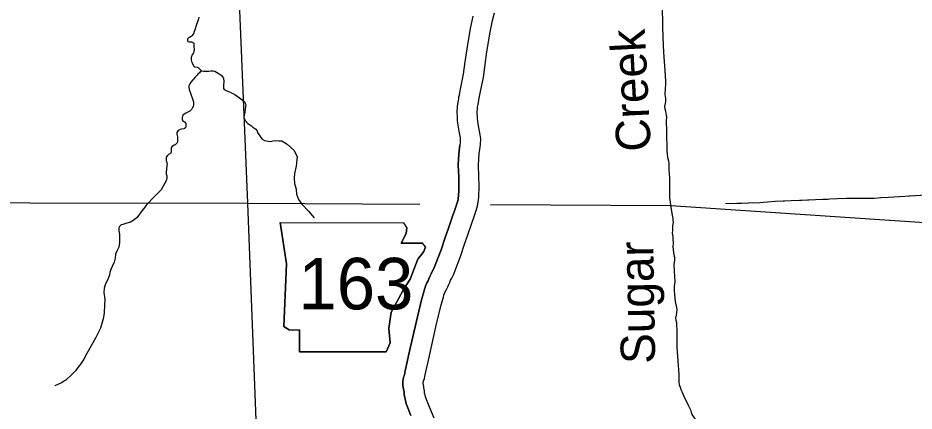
# Model space of a CAD drawing. Extents: x 1720274 to 1751788, y 372074 to 391887.
# Drawn here: x 1732023 to 1733764, y 380014 to 380778 of the extents above; entities that cross this region are included whole.
import ezdxf

# ---------------------------------------------------------------- set-up
doc = ezdxf.new("R2010")
doc.units = 0
for name, color, linetype in [('Level 10', 7, 'Continuous'), ('Level 21', 7, 'Continuous'), ('Level 35', 7, 'Continuous'), ('Level 43', 7, 'Continuous'), ('Level 49', 7, 'Continuous'), ('Level 5', 7, 'Continuous')]:
    doc.layers.add(name, color=color, linetype=linetype)

msp = doc.modelspace()

# ---------------------------------------------------------------- linework, layer by layer
at = {"layer": 'Level 10'}
for points in [[(1732921, 380526.3), (1732921.8, 380533.1), (1732922.3, 380543.1), (1732921.2, 380551.1), (1732918.9, 380565.1), (1732917, 380576.1), (1732916.5, 380578.8), (1732916.2, 380581.7), (1732916.1, 380584.1), (1732916.1, 380587.4), (1732915.8, 380590.9), (1732915.7, 380593.2), (1732915.7, 380595.9), (1732915.7, 380597.6), (1732915.9, 380599.9), (1732916.1, 380602.8), (1732916.4, 380604.9), (1732916.7, 380607.3), (1732917.3, 380610), (1732918.1, 380614.3), (1732918.5, 380617.6), (1732919, 380620), (1732919.4, 380622.3), (1732922.7, 380638.6), (1732927.5, 380662.3), (1732931, 380687.6), (1732934.2, 380712.2), (1732940.9, 380750.3), (1732945.4, 380773.2), (1732949.2, 380788.3)], [(1732906.9, 380781.8), (1732902.1, 380757.5), (1732895.1, 380718.2), (1732891.8, 380692.8), (1732888.5, 380668.9), (1732884, 380646.5), (1732880.6, 380629.5), (1732880.3, 380627.7), (1732879.5, 380624.3), (1732879, 380620.3), (1732878.6, 380617.7), (1732877.8, 380614.3), (1732877.2, 380609.9), (1732876.8, 380606.7), (1732876.5, 380603), (1732876.2, 380599), (1732876.2, 380595.9), (1732876.2, 380592.2), (1732876.4, 380588.5), (1732876.6, 380586), (1732876.6, 380582.8), (1732876.9, 380578.6), (1732877.3, 380573.7), (1732878, 380569.5), (1732879.9, 380558.4), (1732882.2, 380545.2), (1732882.6, 380541.5), (1732882.4, 380536.2), (1732881.8, 380530.6)], [(1732797, 380186.6), (1732807.6, 380230.6), (1732811.8, 380245.7), (1732813.2, 380251.1), (1732815.3, 380257), (1732817.9, 380263.1), (1732820.2, 380267.3), (1732821.8, 380271.1), (1732823.6, 380275.6), (1732826.3, 380280.7), (1732828.2, 380285.4), (1732830.8, 380290.1), (1732832.8, 380294.3), (1732845.6, 380327.6), (1732852.8, 380349.6), (1732860.1, 380369.6), (1732867.1, 380390.7), (1732871.7, 380403.1), (1732875.6, 380415.2), (1732877.8, 380423), (1732878.7, 380426.8), (1732878.9, 380428.3), (1732879, 380431.7), (1732879.2, 380435.4), (1732879.6, 380440.3), (1732879.6, 380443.7), (1732879.6, 380448), (1732879.8, 380452.6), (1732879.6, 380468.6), (1732878.9, 380492.1), (1732879, 380505.1), (1732880.4, 380519.7), (1732881.8, 380530.6)], [(1732881.8, 380530.6), (1732880.4, 380519.7), (1732879, 380505.1), (1732878.9, 380492.1), (1732879.6, 380468.6), (1732879.8, 380452.6), (1732879.6, 380448), (1732879.6, 380443.7), (1732879.6, 380440.3), (1732879.2, 380435.4), (1732879, 380431.7), (1732878.9, 380428.3), (1732878.7, 380426.8), (1732877.8, 380423), (1732875.6, 380415.2), (1732871.7, 380403.1), (1732867.1, 380390.7), (1732860.1, 380369.6), (1732852.8, 380349.6), (1732845.6, 380327.6), (1732832.8, 380294.3), (1732830.8, 380290.1), (1732828.2, 380285.4), (1732826.3, 380280.7), (1732823.6, 380275.6), (1732821.8, 380271.1), (1732820.2, 380267.3), (1732817.9, 380263.1), (1732815.3, 380257), (1732813.2, 380251.1), (1732811.8, 380245.7), (1732807.6, 380230.6), (1732797, 380186.6)], [(1732835.5, 380177.6), (1732845.8, 380220.7), (1732849.9, 380235.3), (1732850.9, 380239.2), (1732852.1, 380242.5), (1732853.6, 380246), (1732855.9, 380250.3), (1732858.2, 380255.8), (1732859.5, 380258.8), (1732862.2, 380264.1), (1732864, 380268.4), (1732866.1, 380272.4), (1732869.2, 380278.9), (1732882.8, 380314.3), (1732890.2, 380336.7), (1732897.4, 380356.6), (1732904.4, 380377.5), (1732909.1, 380390.2), (1732913.5, 380403.9), (1732916.1, 380413.2), (1732917.6, 380420), (1732918.2, 380424.8), (1732918.5, 380429.8), (1732918.6, 380433.1), (1732919, 380438.4), (1732919.1, 380443.2), (1732919.1, 380447.2), (1732919.3, 380452.2), (1732919, 380469.5), (1732918.4, 380492.6), (1732918.5, 380503), (1732919.7, 380515.4), (1732921, 380526.3)], [(1732786.8, 380005.8), (1732778.3, 380027.1), (1732777.2, 380031.3), (1732776.3, 380034.7), (1732775.4, 380038.1), (1732774.9, 380039.8), (1732774.3, 380042.9), (1732773.9, 380046.2), (1732773.7, 380048.7), (1732773.4, 380050.8), (1732773, 380053.9), (1732772.7, 380055.8), (1732772.3, 380057.9), (1732772, 380059.7), (1732771.4, 380063.2), (1732771.2, 380067.3), (1732771.3, 380071.4), (1732771.6, 380075.7), (1732772.6, 380080), (1732773.4, 380082.9), (1732774.2, 380085.5), (1732774.7, 380087.3), (1732775.2, 380089.5), (1732775.7, 380092.2), (1732784.2, 380130.3), (1732797, 380186.6)], [(1732797, 380186.6), (1732784.2, 380130.3), (1732775.7, 380092.2), (1732775.2, 380089.5), (1732774.7, 380087.3), (1732774.2, 380085.5), (1732773.4, 380082.9), (1732772.6, 380080), (1732771.6, 380075.7), (1732771.3, 380071.4), (1732771.2, 380067.3), (1732771.4, 380063.2), (1732772, 380059.7), (1732772.3, 380057.9), (1732772.7, 380055.8), (1732773, 380053.9), (1732773.4, 380050.8), (1732773.7, 380048.7), (1732773.9, 380046.2), (1732774.3, 380042.9), (1732774.9, 380039.8), (1732775.4, 380038.1), (1732776.3, 380034.7), (1732777.2, 380031.3), (1732778.3, 380027.1), (1732786.8, 380005.8)], [(1732831.8, 380000.2), (1732823.4, 380020.6), (1732815.9, 380039.7), (1732815.3, 380041.7), (1732814.4, 380044.9), (1732813.6, 380048.2), (1732813.5, 380048.5), (1732813.4, 380049), (1732813.2, 380050.1), (1732813, 380053.5), (1732812.4, 380056.8), (1732812.1, 380059.2), (1732811.7, 380062.2), (1732811.1, 380065.3), (1732810.9, 380066.7), (1732810.8, 380067.3), (1732810.7, 380067.8), (1732810.8, 380069.6), (1732810.8, 380069.6), (1732810.9, 380070.2), (1732811.4, 380072), (1732812.1, 380074.5), (1732813, 380077.4), (1732813.9, 380081.4), (1732814.4, 380084.3), (1732822.7, 380121.6), (1732835.5, 380177.6)]]:
    msp.add_lwpolyline(points, dxfattribs=at)
at = {"layer": 'Level 21'}
for p, q in [((1732532.9, 380380.4), (1732544.9, 380300.2)), ((1732778.8, 380371), (1732773.3, 380380.2)), ((1732777.5, 380359), (1732778.8, 380371)), ((1732768.1, 380340.3), (1732777.5, 380359)), ((1732809.5, 380340.3), (1732768.1, 380340.3)), ((1732814.9, 380333.6), (1732809.5, 380340.3)), ((1732800.2, 380309.5), (1732812.2, 380324.2)), ((1732812.2, 380324.2), (1732814.9, 380333.6)), ((1732544.9, 380300.2), (1732539.6, 380178.6)), ((1732793.5, 380292.2), (1732800.2, 380309.5)), ((1732785.5, 380270.8), (1732793.5, 380292.2)), ((1732772.1, 380250.7), (1732785.5, 380270.8)), ((1732762.8, 380232), (1732772.1, 380250.7)), ((1732748.1, 380206.6), (1732762.8, 380232)), ((1732744, 380174.5), (1732748.1, 380206.6)), ((1732539.6, 380178.6), (1732550.3, 380171.9)), ((1732550.3, 380171.9), (1732570.3, 380171.9)), ((1732570.3, 380171.9), (1732570.3, 380129.1)), ((1732746.7, 380146.5), (1732744, 380174.5)), ((1732738.7, 380129.1), (1732746.7, 380146.5)), ((1732570.3, 380129.1), (1732738.7, 380129.1))]:
    msp.add_line(p, q, dxfattribs=at)
msp.add_lwpolyline([(1732532.9, 380380.4), (1732773.3, 380380.2)], dxfattribs=at)
at = {"layer": 'Level 35'}
for points in [[(1733275.1, 380802), (1733275.4, 380762.3), (1733276, 380740.9), (1733277.8, 380710.9), (1733280.2, 380675.9), (1733281.5, 380654.9), (1733281.3, 380649), (1733280.6, 380640.9), (1733280.2, 380629.1), (1733281.3, 380621.6), (1733281.1, 380616.8), (1733280.7, 380611.7), (1733279.5, 380606), (1733280, 380601.4), (1733281.5, 380596.7), (1733282.8, 380589.3), (1733283.5, 380586.2), (1733282.8, 380577.6), (1733283.5, 380557.9), (1733284, 380518.9), (1733285.5, 380507.4), (1733287.1, 380500.4), (1733287.9, 380495.3), (1733287.9, 380491.3), (1733287.7, 380482.7), (1733289, 380467.5), (1733289, 380428.1), (1733290.2, 380421), (1733291.3, 380414), (1733293.5, 380397.9), (1733295.4, 380388.6), (1733295.9, 380384.4), (1733296.1, 380380.5), (1733295.9, 380377.6), (1733295.2, 380374), (1733295, 380370.3), (1733294.8, 380365), (1733294.6, 380359.9), (1733295.7, 380352.9), (1733295.7, 380348), (1733296.3, 380341.4), (1733295.6, 380333.2), (1733296.1, 380328.8), (1733297.2, 380321.8), (1733298.8, 380311.7), (1733298.8, 380307.3), (1733297.7, 380299.3), (1733298.1, 380286.1), (1733299, 380275.9), (1733299.6, 380265.4), (1733298.5, 380256.1), (1733298.5, 380249), (1733298.8, 380240), (1733299.2, 380234.2), (1733300.3, 380227), (1733302.5, 380215.3), (1733303.2, 380211.1), (1733302.7, 380205.6), (1733302.1, 380200.8), (1733300.9, 380194.8), (1733301.6, 380191.1), (1733303, 380186.6), (1733303.6, 380166.6), (1733303.2, 380137.7), (1733307.3, 380085.4), (1733307, 380070.7)], [(1732374.8, 380779.3), (1732373.9, 380775.5), (1732371.8, 380768.9), (1732370.5, 380765.5), (1732366.9, 380754.7), (1732365.5, 380751.8), (1732365.1, 380749.5), (1732364.8, 380747.8), (1732364, 380746.3), (1732361.4, 380743.3), (1732360.1, 380742), (1732356.4, 380740.1), (1732354.2, 380738.5), (1732352.9, 380737.5), (1732352.6, 380736.7), (1732352.6, 380735.6), (1732352.6, 380734.6), (1732352.6, 380733.7), (1732353, 380733.3), (1732353.6, 380732.5), (1732355.4, 380732), (1732357.8, 380732), (1732360.4, 380731.7), (1732362.3, 380731.2), (1732363.3, 380730.7), (1732364.8, 380729.4), (1732365.2, 380727.6), (1732365.2, 380725.3), (1732365.3, 380721.7), (1732365.9, 380717), (1732365.9, 380715.2), (1732365.3, 380713.3), (1732365.1, 380711.4), (1732363.6, 380708.8), (1732361.4, 380705.7), (1732360.4, 380703.3), (1732359.7, 380701.5), (1732359.7, 380699.7), (1732359.7, 380697.6), (1732360.4, 380693.6), (1732361.6, 380691.1), (1732364.3, 380684.9), (1732366.6, 380683.1), (1732367.8, 380683), (1732371.7, 380682.7), (1732373.4, 380681.8), (1732376.3, 380679.2), (1732377.8, 380677.1), (1732379.8, 380675.3), (1732383.6, 380674.6), (1732385.9, 380674.6), (1732388.8, 380674.4), (1732394.4, 380674.9), (1732398.3, 380675.6), (1732402.5, 380675.3), (1732405.9, 380674.4), (1732409.3, 380673), (1732412.4, 380670.8), (1732418.3, 380666.9)], [(1732379.5, 380675.7), (1732376, 380671.6), (1732372.6, 380668.6), (1732371.4, 380667.2), (1732369.1, 380664.5), (1732367.7, 380662.9), (1732364.2, 380658.9), (1732363.2, 380658.1), (1732359, 380653.2), (1732357.5, 380650.3), (1732355.5, 380646.1), (1732355.1, 380643.4), (1732355.9, 380639.2), (1732359.5, 380629.7), (1732362.4, 380621.2), (1732364.2, 380614.8), (1732364.2, 380610.5), (1732364.2, 380607.1), (1732362.1, 380602.8), (1732360.6, 380600.4), (1732357.2, 380597.1), (1732353.4, 380595.1), (1732348, 380592.5), (1732343.9, 380589.2), (1732343.4, 380588.1), (1732342.4, 380585), (1732342.4, 380583), (1732342.4, 380580.7), (1732342.9, 380578.9), (1732347, 380576.1), (1732349.3, 380572.7), (1732349.5, 380570.4), (1732349.5, 380567.6), (1732348.8, 380564.5), (1732347, 380563), (1732345.4, 380562.5), (1732341.1, 380561.7), (1732338.5, 380561.4), (1732334.9, 380559.1), (1732332.1, 380555.3), (1732331.9, 380552.2), (1732333.6, 380547.3), (1732333.6, 380542.4), (1732333.1, 380538.3), (1732332.4, 380535.5), (1732330.6, 380533.2), (1732328.5, 380531.4), (1732327, 380530.6), (1732322.4, 380527.8), (1732321.3, 380525.8), (1732321.3, 380522.9), (1732321.3, 380521.1), (1732321.3, 380518.3), (1732320.1, 380515.5), (1732316, 380512.7), (1732313.6, 380510.6), (1732311.3, 380507.8), (1732311.1, 380506), (1732311.1, 380503.2), (1732311.6, 380500.9), (1732313.1, 380494.7), (1732312.9, 380490.8), (1732311.1, 380478.3), (1732311.6, 380474.9), (1732312.4, 380471.3), (1732312.4, 380467.2), (1732311.3, 380461.6), (1732309, 380457.2), (1732301.3, 380444.4), (1732294.2, 380436.7), (1732287.2, 380429.8), (1732273.9, 380415.6), (1732260.6, 380398.7), (1732255.2, 380390.2), (1732247.2, 380384.3), (1732241.8, 380381), (1732234.9, 380379.5), (1732227.2, 380376.9), (1732223.9, 380375.9), (1732220.6, 380372.8), (1732219.3, 380370), (1732219.5, 380364.3), (1732220.6, 380358.2), (1732220.8, 380349.4), (1732220.6, 380342), (1732219.3, 380333), (1732215.2, 380324.8), (1732213.1, 380318.9), (1732212.1, 380311.4), (1732210.3, 380303.7), (1732206.2, 380295.3), (1732203.9, 380289.4), (1732201.8, 380283.5), (1732201.3, 380278.1), (1732199.5, 380273.7), (1732197.2, 380268.3), (1732193.6, 380261.6), (1732191.1, 380253.2), (1732190.3, 380244.2), (1732191.3, 380237), (1732192.3, 380229.8)], [(1732418.3, 380666.9), (1732420.5, 380663.9), (1732422.4, 380661), (1732422.7, 380659.4), (1732423.4, 380655.8), (1732423.4, 380653), (1732422.9, 380648.8), (1732422.8, 380645.9), (1732422.7, 380643.6), (1732422.7, 380642), (1732422.9, 380641.1), (1732424.1, 380639.2), (1732425.3, 380638.1), (1732428.9, 380636.3), (1732434.4, 380634.3), (1732444.8, 380629.1), (1732451.2, 380624.9), (1732453.6, 380622.6), (1732459.1, 380618.8), (1732462.2, 380616.5), (1732463.9, 380614.2), (1732464.9, 380611.9), (1732465.8, 380609), (1732465.6, 380605.3), (1732464.9, 380600.9), (1732464.3, 380595.3), (1732463, 380588.3), (1732462.3, 380584.9), (1732462.5, 380582.5), (1732464.6, 380578.8), (1732470.1, 380573), (1732477.2, 380568.4), (1732480, 380565.8), (1732485.5, 380561.7), (1732487.9, 380558.4), (1732489, 380555.2), (1732491.3, 380551.9), (1732493, 380548.7), (1732495, 380545.7), (1732498.1, 380542.6), (1732502.4, 380539.7), (1732509.9, 380538.4), (1732513.8, 380538.3), (1732518.9, 380539.4), (1732523.5, 380540), (1732529.9, 380539.4), (1732535.7, 380539.4), (1732546.1, 380532.8), (1732559.6, 380521.4), (1732565.8, 380509), (1732565.3, 380503.3), (1732563.8, 380489.8), (1732560.6, 380475.8), (1732560.1, 380467), (1732560.6, 380456.1), (1732563.8, 380445.2), (1732564.8, 380435.9), (1732568.4, 380425.5), (1732574.6, 380416.2), (1732588.1, 380402.7), (1732598.6, 380389.8)], [(1732192.3, 380229.8), (1732191.6, 380221.3), (1732190.8, 380204.4), (1732188.8, 380193.1), (1732183.9, 380175.4), (1732174.9, 380157.4), (1732157.2, 380125.9), (1732151.1, 380115.1), (1732144.9, 380105.1), (1732139.8, 380098.9), (1732135.2, 380092.5), (1732127.2, 380084.8), (1732116.4, 380074.3), (1732108.2, 380068.9), (1732094.9, 380063.5)], [(1733307, 380070.7), (1733307.8, 380065.6), (1733310.6, 380058.5), (1733311.5, 380055), (1733312.8, 380052.2), (1733316.9, 380043.4), (1733326.3, 380024.6), (1733329.9, 380016.8), (1733331.2, 380011.4), (1733332.8, 380007.5), (1733337, 380001.3), (1733343.4, 379994), (1733356.4, 379982.6), (1733372.9, 379965.2)]]:
    msp.add_lwpolyline(points, dxfattribs=at)
at = {"layer": 'Level 43'}
for points in [[(1733397.9, 380417.4), (1733464.5, 380419.5), (1733494.6, 380421.9), (1733572.8, 380425.2), (1733614.9, 380427), (1733632.8, 380427.7), (1733654.6, 380428.1), (1733686.8, 380428.1), (1733700.4, 380428.9), (1733714.4, 380429.7), (1733746.3, 380432), (1733837.2, 380437.5), (1733888.1, 380440.2), (1733929.7, 380442.9), (1733949.1, 380443.7), (1733957.6, 380444.9), (1733969.7, 380447.2), (1733989.2, 380452)], [(1733450, 380419.1), (1733464.5, 380419.5), (1733494.6, 380421.9), (1733512.4, 380422.7)], [(1733533.3, 380423.5), (1733572.8, 380425.2), (1733595.8, 380426.2)], [(1733616.6, 380427), (1733632.8, 380427.7), (1733654.6, 380428.1), (1733679.2, 380428.1)], [(1733700, 380428.9), (1733700.4, 380428.9), (1733714.4, 380429.7), (1733746.3, 380432), (1733762.4, 380433)], [(1733397.9, 380417.4), (1733429.1, 380418.4)]]:
    msp.add_lwpolyline(points, dxfattribs=at)
at = {"layer": 'Level 49'}
for p, q in [((1732544.9, 380300.2), (1732532.9, 380380.4)), ((1732778.8, 380371), (1732777.5, 380359)), ((1732777.5, 380359), (1732768.1, 380340.3)), ((1732768.1, 380340.3), (1732809.5, 380340.3)), ((1732812.2, 380324.2), (1732800.2, 380309.5)), ((1732814.9, 380333.6), (1732812.2, 380324.2)), ((1732539.6, 380178.6), (1732544.9, 380300.2)), ((1732800.2, 380309.5), (1732793.5, 380292.2)), ((1732793.5, 380292.2), (1732785.5, 380270.8)), ((1732785.5, 380270.8), (1732772.1, 380250.7)), ((1732772.1, 380250.7), (1732762.8, 380232)), ((1732762.8, 380232), (1732748.1, 380206.6)), ((1732748.1, 380206.6), (1732744, 380174.5)), ((1732550.3, 380171.9), (1732539.6, 380178.6)), ((1732570.3, 380129.1), (1732570.3, 380171.9)), ((1732744, 380174.5), (1732746.7, 380146.5)), ((1732746.7, 380146.5), (1732738.7, 380129.1)), ((1732738.7, 380129.1), (1732570.3, 380129.1))]:
    msp.add_line(p, q, dxfattribs=at)
msp.add_lwpolyline([(1732532.9, 380380.4), (1732773.3, 380380.2)], dxfattribs=at)
at = {"layer": 'Level 5'}
for points in [[(1732434.1, 381262.1), (1732469.3, 380417.9)], [(1731623, 380419.3), (1732469.3, 380417.9)], [(1732469.3, 380417.9), (1732501.6, 379574.7)], [(1732469.3, 380417.9), (1732803.8, 380416.1)], [(1732941.4, 380415.4), (1733291.7, 380413.5)], [(1733291.7, 380413.5), (1734056.1, 380362.4)]]:
    msp.add_lwpolyline(points, dxfattribs=at)

# ---------------------------------------------------------------- texts
at = {"layer": 'Level 21'}
msp.add_text('163', height=100.11, dxfattribs=at).set_placement((1732568.2, 380211.8))
at = {"layer": 'Level 35'}
for s, rotation, p in [('Creek', 92.9404, (1733253.2, 380520)), ('Sugar', 90.9873, (1733261.5, 380106.4))]:
    msp.add_text(s, height=66.74, rotation=rotation, dxfattribs=at).set_placement(p)
at = {"layer": 'Level 49'}
msp.add_text('163', height=100.11, dxfattribs=at).set_placement((1732568.2, 380211.8))

doc.saveas('drawing.dxf')
